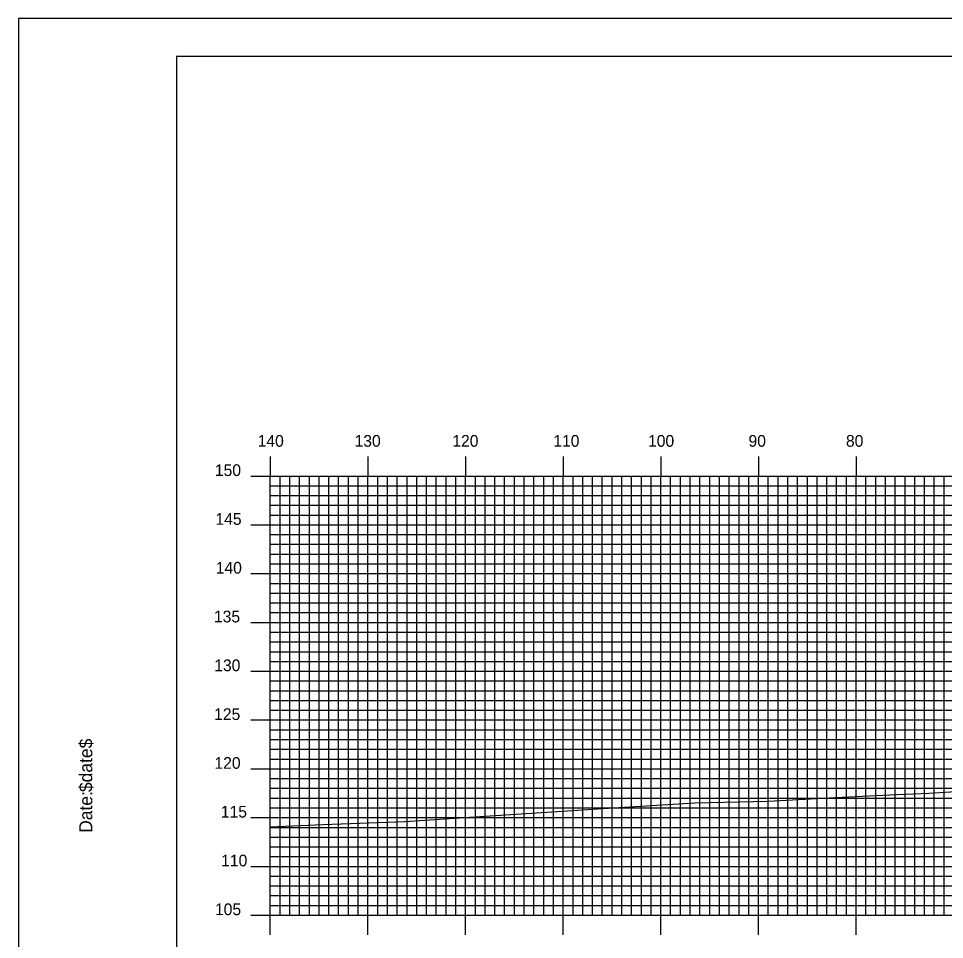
# Model space of a CAD drawing. Extents: x 1782254 to 1782597, y 442591 to 442811.
# Drawn here: x 1782253.6 to 1782348.5, y 442716.2 to 442810.5 of the extents above; entities that cross this region are included whole.
import ezdxf

# ---------------------------------------------------------------- set-up
doc = ezdxf.new("R2010")
doc.units = 0
for name, color, linetype in [('BORDER', 7, 'Continuous'), ('H_V ANNOTATION', 7, 'Continuous'), ('MAJOR', 7, 'Continuous'), ('MINOR', 7, 'Continuous'), ('PLOT BOUNDARY', 7, 'Continuous'), ('S_Roadway_Centerline', 7, 'Continuous')]:
    doc.layers.add(name, color=color, linetype=linetype)

msp = doc.modelspace()

# ---------------------------------------------------------------- linework, layer by layer
at = {"layer": 'BORDER'}
msp.add_lwpolyline([(1782269.834, 442596.665), (1782589.834, 442596.665), (1782589.834, 442806.665), (1782269.834, 442806.665)], close=True, dxfattribs=at)
at = {"layer": 'MAJOR'}
for p, q in [((1782279.434, 442765.669), (1782279.434, 442763.665)), ((1782289.434, 442765.669), (1782289.434, 442763.665)), ((1782299.434, 442765.669), (1782299.434, 442763.665)), ((1782309.434, 442765.669), (1782309.434, 442763.665)), ((1782319.434, 442765.669), (1782319.434, 442763.665)), ((1782329.434, 442765.669), (1782329.434, 442763.665)), ((1782339.434, 442765.669), (1782339.434, 442763.665)), ((1782277.43, 442763.665), (1782279.434, 442763.665)), ((1782279.434, 442763.665), (1782559.434, 442763.665)), ((1782279.434, 442718.665), (1782279.434, 442763.665)), ((1782279.434, 442718.665), (1782279.434, 442763.665)), ((1782279.434, 442763.665), (1782559.434, 442763.665)), ((1782289.434, 442718.665), (1782289.434, 442763.665)), ((1782299.434, 442718.665), (1782299.434, 442763.665)), ((1782309.434, 442718.665), (1782309.434, 442763.665)), ((1782319.434, 442718.665), (1782319.434, 442763.665)), ((1782329.434, 442718.665), (1782329.434, 442763.665)), ((1782339.434, 442718.665), (1782339.434, 442763.665)), ((1782277.43, 442758.665), (1782279.434, 442758.665)), ((1782279.434, 442758.665), (1782559.434, 442758.665)), ((1782277.43, 442753.665), (1782279.434, 442753.665)), ((1782279.434, 442753.665), (1782559.434, 442753.665)), ((1782277.43, 442748.665), (1782279.434, 442748.665)), ((1782279.434, 442748.665), (1782559.434, 442748.665)), ((1782277.43, 442743.665), (1782279.434, 442743.665)), ((1782279.434, 442743.665), (1782559.434, 442743.665)), ((1782277.43, 442738.665), (1782279.434, 442738.665)), ((1782279.434, 442738.665), (1782559.434, 442738.665)), ((1782277.43, 442733.665), (1782279.434, 442733.665)), ((1782279.434, 442733.665), (1782559.434, 442733.665)), ((1782277.43, 442728.665), (1782279.434, 442728.665)), ((1782279.434, 442728.665), (1782559.434, 442728.665)), ((1782277.43, 442723.665), (1782279.434, 442723.665)), ((1782279.434, 442723.665), (1782559.434, 442723.665)), ((1782277.43, 442718.665), (1782279.434, 442718.665)), ((1782279.434, 442718.665), (1782559.434, 442718.665)), ((1782279.434, 442718.665), (1782559.434, 442718.665)), ((1782279.434, 442716.661), (1782279.434, 442718.665)), ((1782289.434, 442716.661), (1782289.434, 442718.665)), ((1782299.434, 442716.661), (1782299.434, 442718.665)), ((1782309.434, 442716.661), (1782309.434, 442718.665)), ((1782319.434, 442716.661), (1782319.434, 442718.665)), ((1782329.434, 442716.661), (1782329.434, 442718.665)), ((1782339.434, 442716.661), (1782339.434, 442718.665))]:
    msp.add_line(p, q, dxfattribs=at)
at = {"layer": 'MINOR'}
for p, q in [((1782280.434, 442718.665), (1782280.434, 442763.665)), ((1782281.434, 442718.665), (1782281.434, 442763.665)), ((1782282.434, 442718.665), (1782282.434, 442763.665)), ((1782283.434, 442718.665), (1782283.434, 442763.665)), ((1782284.434, 442718.665), (1782284.434, 442763.665)), ((1782285.434, 442718.665), (1782285.434, 442763.665)), ((1782286.434, 442718.665), (1782286.434, 442763.665)), ((1782287.434, 442718.665), (1782287.434, 442763.665)), ((1782288.434, 442718.665), (1782288.434, 442763.665)), ((1782290.434, 442718.665), (1782290.434, 442763.665)), ((1782291.434, 442718.665), (1782291.434, 442763.665)), ((1782292.434, 442718.665), (1782292.434, 442763.665)), ((1782293.434, 442718.665), (1782293.434, 442763.665)), ((1782294.434, 442718.665), (1782294.434, 442763.665)), ((1782295.434, 442718.665), (1782295.434, 442763.665)), ((1782296.434, 442718.665), (1782296.434, 442763.665)), ((1782297.434, 442718.665), (1782297.434, 442763.665)), ((1782298.434, 442718.665), (1782298.434, 442763.665)), ((1782300.434, 442718.665), (1782300.434, 442763.665)), ((1782301.434, 442718.665), (1782301.434, 442763.665)), ((1782302.434, 442718.665), (1782302.434, 442763.665)), ((1782303.434, 442718.665), (1782303.434, 442763.665)), ((1782304.434, 442718.665), (1782304.434, 442763.665)), ((1782305.434, 442718.665), (1782305.434, 442763.665)), ((1782306.434, 442718.665), (1782306.434, 442763.665)), ((1782307.434, 442718.665), (1782307.434, 442763.665)), ((1782308.434, 442718.665), (1782308.434, 442763.665)), ((1782310.434, 442718.665), (1782310.434, 442763.665)), ((1782311.434, 442718.665), (1782311.434, 442763.665)), ((1782312.434, 442718.665), (1782312.434, 442763.665)), ((1782313.434, 442718.665), (1782313.434, 442763.665)), ((1782314.434, 442718.665), (1782314.434, 442763.665)), ((1782315.434, 442718.665), (1782315.434, 442763.665)), ((1782316.434, 442718.665), (1782316.434, 442763.665)), ((1782317.434, 442718.665), (1782317.434, 442763.665)), ((1782318.434, 442718.665), (1782318.434, 442763.665)), ((1782320.434, 442718.665), (1782320.434, 442763.665)), ((1782321.434, 442718.665), (1782321.434, 442763.665)), ((1782322.434, 442718.665), (1782322.434, 442763.665)), ((1782323.434, 442718.665), (1782323.434, 442763.665)), ((1782324.434, 442718.665), (1782324.434, 442763.665)), ((1782325.434, 442718.665), (1782325.434, 442763.665)), ((1782326.434, 442718.665), (1782326.434, 442763.665)), ((1782327.434, 442718.665), (1782327.434, 442763.665)), ((1782328.434, 442718.665), (1782328.434, 442763.665)), ((1782330.434, 442718.665), (1782330.434, 442763.665)), ((1782331.434, 442718.665), (1782331.434, 442763.665)), ((1782332.434, 442718.665), (1782332.434, 442763.665)), ((1782333.434, 442718.665), (1782333.434, 442763.665)), ((1782334.434, 442718.665), (1782334.434, 442763.665)), ((1782335.434, 442718.665), (1782335.434, 442763.665)), ((1782336.434, 442718.665), (1782336.434, 442763.665)), ((1782337.434, 442718.665), (1782337.434, 442763.665)), ((1782338.434, 442718.665), (1782338.434, 442763.665)), ((1782340.434, 442718.665), (1782340.434, 442763.665)), ((1782341.434, 442718.665), (1782341.434, 442763.665)), ((1782342.434, 442718.665), (1782342.434, 442763.665)), ((1782343.434, 442718.665), (1782343.434, 442763.665)), ((1782344.434, 442718.665), (1782344.434, 442763.665)), ((1782345.434, 442718.665), (1782345.434, 442763.665)), ((1782346.434, 442718.665), (1782346.434, 442763.665)), ((1782347.434, 442718.665), (1782347.434, 442763.665)), ((1782348.434, 442718.665), (1782348.434, 442763.665)), ((1782279.434, 442762.665), (1782559.434, 442762.665)), ((1782279.434, 442762.665), (1782281.438, 442762.665)), ((1782279.434, 442761.665), (1782559.434, 442761.665)), ((1782279.434, 442761.665), (1782281.438, 442761.665)), ((1782279.434, 442760.665), (1782559.434, 442760.665)), ((1782279.434, 442760.665), (1782281.438, 442760.665)), ((1782279.434, 442759.665), (1782559.434, 442759.665)), ((1782279.434, 442759.665), (1782281.438, 442759.665)), ((1782279.434, 442757.665), (1782559.434, 442757.665)), ((1782279.434, 442757.665), (1782281.438, 442757.665)), ((1782279.434, 442756.665), (1782559.434, 442756.665)), ((1782279.434, 442756.665), (1782281.438, 442756.665)), ((1782279.434, 442755.665), (1782559.434, 442755.665)), ((1782279.434, 442755.665), (1782281.438, 442755.665)), ((1782279.434, 442754.665), (1782559.434, 442754.665)), ((1782279.434, 442754.665), (1782281.438, 442754.665)), ((1782279.434, 442752.665), (1782559.434, 442752.665)), ((1782279.434, 442752.665), (1782281.438, 442752.665)), ((1782279.434, 442751.665), (1782559.434, 442751.665)), ((1782279.434, 442751.665), (1782281.438, 442751.665)), ((1782279.434, 442750.665), (1782559.434, 442750.665)), ((1782279.434, 442750.665), (1782281.438, 442750.665)), ((1782279.434, 442749.665), (1782559.434, 442749.665)), ((1782279.434, 442749.665), (1782281.438, 442749.665)), ((1782279.434, 442747.665), (1782559.434, 442747.665)), ((1782279.434, 442747.665), (1782281.438, 442747.665)), ((1782279.434, 442746.665), (1782559.434, 442746.665)), ((1782279.434, 442746.665), (1782281.438, 442746.665)), ((1782279.434, 442745.665), (1782559.434, 442745.665)), ((1782279.434, 442745.665), (1782281.438, 442745.665)), ((1782279.434, 442744.665), (1782559.434, 442744.665)), ((1782279.434, 442744.665), (1782281.438, 442744.665)), ((1782279.434, 442742.665), (1782559.434, 442742.665)), ((1782279.434, 442742.665), (1782281.438, 442742.665)), ((1782279.434, 442741.665), (1782559.434, 442741.665)), ((1782279.434, 442741.665), (1782281.438, 442741.665)), ((1782279.434, 442740.665), (1782559.434, 442740.665)), ((1782279.434, 442740.665), (1782281.438, 442740.665)), ((1782279.434, 442739.665), (1782559.434, 442739.665)), ((1782279.434, 442739.665), (1782281.438, 442739.665)), ((1782279.434, 442737.665), (1782559.434, 442737.665)), ((1782279.434, 442737.665), (1782281.438, 442737.665)), ((1782279.434, 442736.665), (1782559.434, 442736.665)), ((1782279.434, 442736.665), (1782281.438, 442736.665)), ((1782279.434, 442735.665), (1782559.434, 442735.665)), ((1782279.434, 442735.665), (1782281.438, 442735.665)), ((1782279.434, 442734.665), (1782559.434, 442734.665)), ((1782279.434, 442734.665), (1782281.438, 442734.665)), ((1782279.434, 442732.665), (1782559.434, 442732.665)), ((1782279.434, 442732.665), (1782281.438, 442732.665)), ((1782279.434, 442731.665), (1782559.434, 442731.665)), ((1782279.434, 442731.665), (1782281.438, 442731.665)), ((1782279.434, 442730.665), (1782559.434, 442730.665)), ((1782279.434, 442730.665), (1782281.438, 442730.665)), ((1782279.434, 442729.665), (1782559.434, 442729.665)), ((1782279.434, 442729.665), (1782281.438, 442729.665)), ((1782279.434, 442727.665), (1782559.434, 442727.665)), ((1782279.434, 442727.665), (1782281.438, 442727.665)), ((1782279.434, 442726.665), (1782559.434, 442726.665)), ((1782279.434, 442726.665), (1782281.438, 442726.665)), ((1782279.434, 442725.665), (1782559.434, 442725.665)), ((1782279.434, 442725.665), (1782281.438, 442725.665)), ((1782279.434, 442724.665), (1782559.434, 442724.665)), ((1782279.434, 442724.665), (1782281.438, 442724.665)), ((1782279.434, 442722.665), (1782559.434, 442722.665)), ((1782279.434, 442722.665), (1782281.438, 442722.665)), ((1782279.434, 442721.665), (1782559.434, 442721.665)), ((1782279.434, 442721.665), (1782281.438, 442721.665)), ((1782279.434, 442720.665), (1782559.434, 442720.665)), ((1782279.434, 442720.665), (1782281.438, 442720.665)), ((1782279.434, 442719.665), (1782559.434, 442719.665)), ((1782279.434, 442719.665), (1782281.438, 442719.665))]:
    msp.add_line(p, q, dxfattribs=at)
at = {"layer": 'PLOT BOUNDARY'}
msp.add_lwpolyline([(1782253.647, 442590.547), (1782593.647, 442590.547), (1782593.647, 442810.547), (1782253.647, 442810.547)], close=True, dxfattribs=at)
at = {"layer": 'S_Roadway_Centerline'}
msp.add_lwpolyline([(1782279.434, 442727.703), (1782284.853, 442727.953), (1782293.197, 442728.272), (1782299.329, 442728.66), (1782314.567, 442729.657), (1782322.922, 442730.163), (1782330.429, 442730.336), (1782337.298, 442730.724), (1782342.88, 442731.003), (1782346.891, 442731.172), (1782359.715, 442731.963)], dxfattribs=at)

# ---------------------------------------------------------------- texts
at = {"layer": 'BORDER'}
for s, p in [('$date$', (1782261.204, 442731.275)), ('$date$', (1782261.204, 442731.275)), ('Date:', (1782261.204, 442727.099)), ('Date:', (1782261.204, 442727.099))]:
    msp.add_text(s, height=1.3392, rotation=90, dxfattribs=at).set_placement(p)
at = {"layer": 'H_V ANNOTATION'}
for s, p in [('140', (1782278.139, 442766.665)), ('130', (1782288.064, 442766.665)), ('120', (1782298.074, 442766.665)), ('110', (1782308.417, 442766.665)), ('100', (1782318.117, 442766.665)), ('90', (1782328.406, 442766.665)), ('80', (1782338.385, 442766.665)), ('150', (1782273.758, 442763.665)), ('145', (1782273.812, 442758.665)), ('140', (1782273.844, 442753.665)), ('135', (1782273.662, 442748.665)), ('130', (1782273.694, 442743.665)), ('125', (1782273.683, 442738.665)), ('120', (1782273.715, 442733.665)), ('115', (1782274.368, 442728.665)), ('110', (1782274.4, 442723.665)), ('105', (1782273.769, 442718.665))]:
    msp.add_text(s, height=1.2, dxfattribs=at).set_placement(p)
at = {"layer": 'MAJOR'}
msp.add_text('-', height=0.012, dxfattribs=at).set_placement((1782279.425, 442718.665))

doc.saveas('drawing.dxf')
